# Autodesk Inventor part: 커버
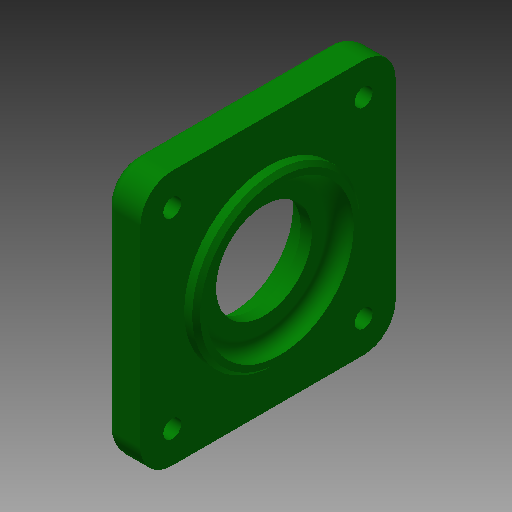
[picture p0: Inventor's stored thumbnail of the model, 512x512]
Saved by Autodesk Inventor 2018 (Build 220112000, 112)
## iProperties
Created: 2019-09
Part Number: 커버
Material: 알루미늄 6061
Document SubType Name: Modeling
Designer: mduedu
Density: 2.71 g/cm^3
Appearance: 진녹색
Mass: 80.7314 g
Surface Area: 109.271 cm^2
Volume: 29.7902 cm^3
Author: mduedu
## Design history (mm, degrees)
sketch "스케치1"
  geometry: L1 (-32, -32)-(32, -32); L2 (32, -32)-(32, 32); L3 (32, 32)-(-32, 32); L4 (-32, 32)-(-32, -32); L5 (-32, -32)-(32, 32); L6 (32, -32)-(-32, 32); 1 further point
  constraints: 12 end point, 2 midpoint, 2 parallel, 1 horizontal, 1 perpendicular
  dimensions: "d44" = 64 distance of L3.end L2.end; "d45" = 64 distance of L2.end L1.end
extrude "돌출1" new body sketch "스케치1" distance "d1" = 9; taper "d2" = 0 deg
sketch "스케치2"
  geometry: C1 r 21 at (0, 0); 1 further point
  constraints: 1 centre point, 1 coincident
  dimensions: "d3" = 42 diameter of C1
extrude "돌출2" join sketch "스케치2" distance "d4" = 3; taper "d5" = 0 deg
hole "구멍1" diameter "d8" = 24; stored, may be unused: countersink angle "d12" = 90 deg, drill point angle "d14" = 118 deg; dims "d9" = 6, "d10" = 30, "d11" = 5.2, "d13" = 8, "d46" = 10, "d47" = 10
hole "구멍2" diameter "d17" = 37; stored, may be unused: countersink angle "d21" = 90 deg, drill point angle "d23" = 0 deg; dims "d15" = 10, "d16" = 10, "d18" = 6, "d19" = 30, "d20" = 5.2, "d22" = 4
fillet "모깎기1" dims "d24" = 3
fillet "모깎기4" dims "d48" = 8
fillet "모깎기2" dims "d25" = 3
chamfer "모따기1" distance "d27" = 0.5; stored, may be unused: second distance "d28" = 2, angle "d29" = 30 deg
chamfer "모따기2" distance "d30" = 1; stored, may be unused: second distance "d31" = 2, angle "d32" = 30 deg
sketch "스케치4"
  geometry: A1 r 8 centre (-24, 24) between (-24, 32) and (-32, 24) reference; A2 r 8 centre (24, 24) between (32, 24) and (24, 32) reference; A3 r 8 centre (24, -24) between (24, -32) and (32, -24) reference; A4 r 8 centre (-24, -24) between (-32, -24) and (-24, -32) reference; 5 further points
  constraints: 4 coincident
hole "구멍4" sketch "스케치4" at (-24, 24), (24, 24), (24, -24), (-24, -24) diameter "d49" = 4.5; stored, may be unused: countersink angle "d53" = 90 deg, drill point angle "d55" = 118 deg; dims "d50" = 6, "d51" = 8, "d52" = 4.4, "d54" = 8
node "솔리드1"
